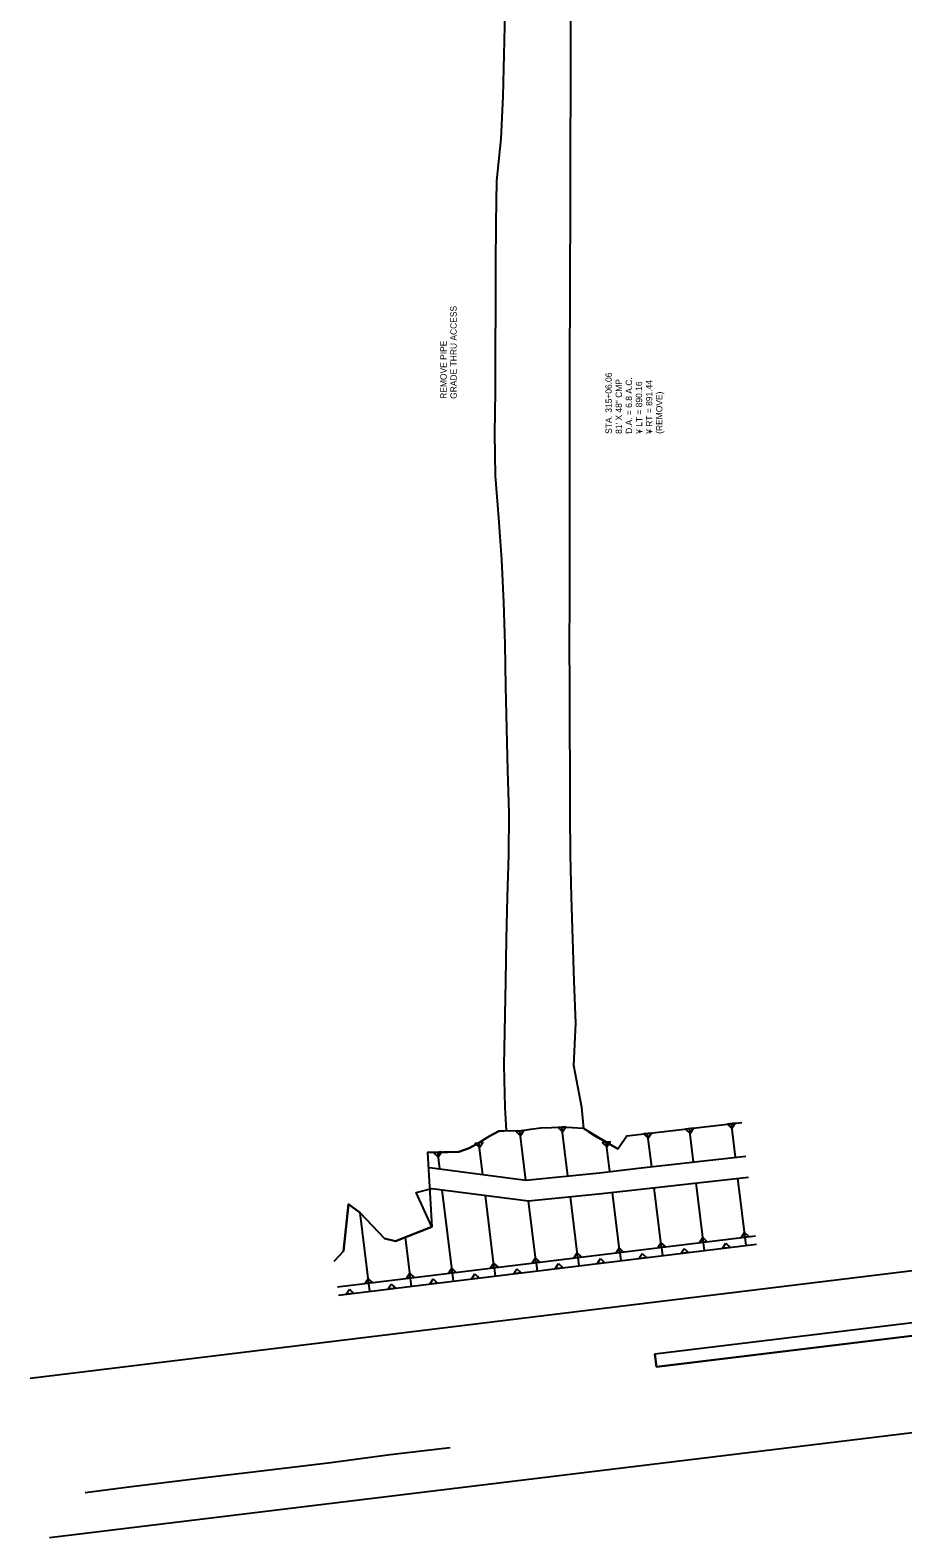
# Model space of a CAD drawing. Extents: x 18436148 to 18440034, y 7649939 to 7652226.
# Drawn here: x 18436148 to 18436563, y 7649939 to 7650654 of the extents above; entities that cross this region are included whole.
import ezdxf

# ---------------------------------------------------------------- set-up
doc = ezdxf.new("R2010")
doc.units = 0
for name, color, linetype in [('dsnCellsScaleBlock', 7, 'Continuous'), ('TC_Subbase', 7, 'Continuous'), ('TL_Backslope', 7, 'Continuous'), ('TL_ShoulderBtm', 7, 'Continuous'), ('TSOUTLINE', 7, 'Continuous'), ('TSWHEELBASE', 7, 'Continuous')]:
    doc.layers.add(name, color=color, linetype=linetype)

msp = doc.modelspace()

# ---------------------------------------------------------------- linework, layer by layer
at = {"layer": 'TC_Subbase'}
for p, q in [((18436383.74, 7650108.48), (18436380.9, 7650131.77)), ((18436403.64, 7650110.46), (18436400.83, 7650133.56)), ((18436443.42, 7650114.76), (18436441.49, 7650130.56)), ((18436463.29, 7650117.01), (18436461.36, 7650132.87)), ((18436483.16, 7650119.26), (18436481.22, 7650135.17)), ((18436363.27, 7650111.1), (18436361.44, 7650126.09)), ((18436423.54, 7650112.51), (18436421.85, 7650126.4)), ((18436342.8, 7650113.72), (18436341.84, 7650121.63)), ((18436488.27, 7650077.35), (18436484.37, 7650109.33)), ((18436349.3, 7650060.42), (18436344.01, 7650103.8)), ((18436428.23, 7650074.06), (18436424.75, 7650102.58)), ((18436448.08, 7650076.48), (18436444.63, 7650104.83)), ((18436468.42, 7650074.93), (18436464.5, 7650107.08)), ((18436368.67, 7650066.81), (18436364.48, 7650101.18)), ((18436388.52, 7650069.22), (18436384.95, 7650098.55)), ((18436408.37, 7650071.64), (18436404.85, 7650100.53)), ((18436309.59, 7650055.58), (18436305.04, 7650092.96)), ((18436294.22, 7650057.73), (18436492.75, 7650081.92)), ((18436329.45, 7650058), (18436326.61, 7650081.28)), ((18436428.23, 7650074.06), (18436428.71, 7650070.09)), ((18436448.08, 7650076.48), (18436448.56, 7650072.51)), ((18436368.67, 7650066.81), (18436369.15, 7650062.84)), ((18436388.52, 7650069.22), (18436389, 7650065.25)), ((18436408.37, 7650071.64), (18436408.86, 7650067.67))]:
    msp.add_line(p, q, dxfattribs=at)
for points in [[(18436337.02, 7650121.61), (18436346.88, 7650121.66), (18436351.89, 7650121.81), (18436356.71, 7650123.63), (18436361.44, 7650126.09), (18436366.12, 7650129.07), (18436370.83, 7650131.72), (18436375.85, 7650131.91), (18436380.9, 7650131.77), (18436385.84, 7650132.59), (18436390.79, 7650133.31), (18436395.81, 7650133.44), (18436400.83, 7650133.56), (18436405.89, 7650133.36), (18436410.96, 7650133.11), (18436413.21, 7650131.57), (18436416.43, 7650129.53), (18436421.85, 7650126.4), (18436427.27, 7650123.29), (18436431.56, 7650129.4), (18436486.19, 7650135.75)], [(18436337.9, 7650114.35), (18436383.74, 7650108.48), (18436418.57, 7650111.94), (18436438.45, 7650114.19), (18436488.13, 7650119.82)], [(18436339.11, 7650104.42), (18436384.95, 7650098.55), (18436419.78, 7650102.02), (18436489.34, 7650109.89)], [(18436292.73, 7650069.95), (18436297.2, 7650074.62), (18436299.5, 7650097.07), (18436305.04, 7650092.96), (18436316.6, 7650080.75), (18436321.8, 7650079.39), (18436339.12, 7650086.22), (18436331.59, 7650102.56), (18436339.11, 7650104.42)]]:
    msp.add_lwpolyline(points, dxfattribs=at)
for points in [[(18436381.17, 7650129.53), (18436382.76, 7650131.99), (18436379.04, 7650131.54)], [(18436401.1, 7650131.33), (18436402.69, 7650133.79), (18436398.97, 7650133.34)], [(18436441.76, 7650128.32), (18436443.35, 7650130.78), (18436439.63, 7650130.33)], [(18436461.63, 7650130.63), (18436463.22, 7650133.09), (18436459.5, 7650132.64)], [(18436481.5, 7650132.94), (18436483.09, 7650135.4), (18436479.36, 7650134.95)], [(18436361.72, 7650123.86), (18436363.31, 7650126.32), (18436359.58, 7650125.86)], [(18436422.12, 7650124.17), (18436423.71, 7650126.63), (18436419.99, 7650126.18)], [(18436342.11, 7650119.4), (18436343.7, 7650121.86), (18436339.98, 7650121.41)], [(18436467.66, 7650081.13), (18436469.79, 7650079.13), (18436466.07, 7650078.67)], [(18436487.51, 7650083.55), (18436489.65, 7650081.55), (18436485.93, 7650081.09)], [(18436408.1, 7650073.88), (18436410.24, 7650071.87), (18436406.51, 7650071.42)], [(18436427.95, 7650076.3), (18436430.09, 7650074.29), (18436426.37, 7650073.84)], [(18436438.92, 7650073.6), (18436441.06, 7650071.6), (18436437.33, 7650071.14)], [(18436447.81, 7650078.72), (18436449.94, 7650076.71), (18436446.22, 7650076.26)], [(18436458.78, 7650076.02), (18436460.91, 7650074.02), (18436457.19, 7650073.56)], [(18436478.63, 7650078.44), (18436480.76, 7650076.43), (18436477.04, 7650075.98)], [(18436348.54, 7650066.62), (18436350.68, 7650064.61), (18436346.95, 7650064.16)], [(18436368.4, 7650069.04), (18436370.53, 7650067.03), (18436366.81, 7650066.58)], [(18436379.36, 7650066.35), (18436381.5, 7650064.34), (18436377.77, 7650063.89)], [(18436388.25, 7650071.46), (18436390.38, 7650069.45), (18436386.66, 7650069)], [(18436399.22, 7650068.77), (18436401.35, 7650066.76), (18436397.63, 7650066.3)], [(18436419.07, 7650071.18), (18436421.2, 7650069.18), (18436417.48, 7650068.72)], [(18436308.84, 7650061.78), (18436310.97, 7650059.78), (18436307.25, 7650059.32)], [(18436319.8, 7650059.09), (18436321.94, 7650057.08), (18436318.21, 7650056.63)], [(18436328.69, 7650064.2), (18436330.82, 7650062.19), (18436327.1, 7650061.74)], [(18436339.66, 7650061.51), (18436341.79, 7650059.5), (18436338.07, 7650059.05)], [(18436359.51, 7650063.93), (18436361.64, 7650061.92), (18436357.92, 7650061.47)], [(18436299.95, 7650056.67), (18436302.08, 7650054.66), (18436298.36, 7650054.21)]]:
    msp.add_lwpolyline(points, close=True, dxfattribs=at)
at = {"layer": 'TL_Backslope'}
msp.add_line((18436294.7, 7650053.76), (18436493.23, 7650077.95), dxfattribs=at)
msp.add_lwpolyline([(18436347.8, 7649981.35), (18436319.22, 7649978), (18436291.1, 7649974.28), (18436255.59, 7649969.91), (18436230.04, 7649966.89), (18436195.29, 7649962.62), (18436174.46, 7649959.96)], dxfattribs=at)
at = {"layer": 'TL_ShoulderBtm'}
for p, q in [((18438530.78, 7650304.56), (18436148.4, 7650014.28)), ((18438540.01, 7650228.87), (18436157.63, 7649938.59))]:
    msp.add_line(p, q, dxfattribs=at)
at = {"layer": 'TSOUTLINE'}
for points in [[(18436374.42, 7650131.95), (18436373.93, 7650142.85), (18436373.33, 7650162.85), (18436374.2, 7650202.85), (18436374.57, 7650222.85), (18436375.04, 7650242.85), (18436375.66, 7650262.85), (18436375.71, 7650282.85), (18436375.12, 7650302.85), (18436374.63, 7650322.85), (18436374.24, 7650342.85), (18436373.86, 7650362.85), (18436373.18, 7650382.85), (18436372.25, 7650402.85), (18436370.81, 7650422.84), (18436369.34, 7650442.84), (18436369.01, 7650462.84), (18436369.2, 7650482.84), (18436369.22, 7650502.84), (18436369.39, 7650522.84), (18436369.48, 7650542.84), (18436369.54, 7650562.84), (18436369.89, 7650582.84), (18436371.9, 7650602.85), (18436372.85, 7650622.85), (18436373.43, 7650642.85), (18436373.89, 7650662.85)], [(18436411.18, 7650132.96), (18436410.33, 7650142.91), (18436406.5, 7650162.9), (18436407.43, 7650182.91), (18436406.64, 7650202.9), (18436405.97, 7650222.9), (18436405.35, 7650242.9), (18436404.81, 7650262.9), (18436404.73, 7650282.93), (18436404.67, 7650302.9), (18436404.59, 7650322.9), (18436404.49, 7650342.9), (18436404.47, 7650362.9), (18436404.57, 7650382.9), (18436404.61, 7650402.9), (18436404.6, 7650422.9), (18436404.56, 7650442.9), (18436404.49, 7650462.9), (18436404.56, 7650482.9), (18436404.61, 7650502.9), (18436404.68, 7650522.9), (18436404.76, 7650542.9), (18436404.82, 7650562.9), (18436404.91, 7650582.9), (18436404.92, 7650602.9), (18436404.96, 7650622.9), (18436405, 7650642.9), (18436405.03, 7650662.9)], [(18436374.4, 7650131.85), (18436370.83, 7650131.72), (18436366.12, 7650129.07), (18436361.44, 7650126.09), (18436356.71, 7650123.63), (18436351.89, 7650121.81), (18436337.02, 7650121.61), (18436339.12, 7650086.22), (18436321.8, 7650079.39), (18436316.6, 7650080.75), (18436305.04, 7650092.96), (18436299.5, 7650097.07), (18436297.2, 7650074.62), (18436292.73, 7650069.98)], [(18436411.18, 7650132.96), (18436427.27, 7650123.29), (18436431.56, 7650129.4), (18436486.18, 7650135.75)], [(18436569.91, 7650040.96), (18436444.94, 7650025.73), (18436445.66, 7650019.77), (18436570.64, 7650034.99)]]:
    msp.add_lwpolyline(points, dxfattribs=at)
at = {"layer": 'TSWHEELBASE'}
for p, q in [((18437018.03, 7650089.51), (18436445.66, 7650019.77)), ((18436569.91, 7650040.96), (18436444.94, 7650025.73)), ((18436445.66, 7650019.77), (18436444.94, 7650025.73))]:
    msp.add_line(p, q, dxfattribs=at)

# ---------------------------------------------------------------- texts
at = {"layer": 'dsnCellsScaleBlock'}
for s, p in [('GRADE THRU ACCESS', (18436350.88, 7650479.37)), ('REMOVE PIPE', (18436346.08, 7650479.36)), ('STA. 315+06.06', (18436424.5, 7650462.73)), ('81\' X 48" CMP', (18436429.3, 7650462.73)), ('D.A. = 6.8 A.C.', (18436434.1, 7650462.74)), ('¥ LT = 890.16', (18436438.9, 7650462.75)), ('¥ RT = 891.44', (18436443.7, 7650462.75)), ('(REMOVE)', (18436448.5, 7650462.76))]:
    msp.add_text(s, height=3, rotation=90.07765, dxfattribs=at).set_placement(p)

doc.saveas('drawing.dxf')
